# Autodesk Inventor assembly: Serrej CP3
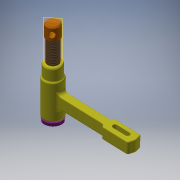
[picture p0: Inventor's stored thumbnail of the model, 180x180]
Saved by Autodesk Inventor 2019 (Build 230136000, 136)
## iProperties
Created: 2019-02
Part Number: Serrej CP3
Material: Générique
Document SubType Name: Assembly
Designer: si-nd67
Author: si-nd67
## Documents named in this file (4)
- E:\ECAM\serrejointsw\Serrej CP3.iam
- E:\ECAM\serrejointsw\Serrej-ACp.iam
- E:\ECAM\serrejointsw\Vis de manoeuvre14.ipt
- E:\ECAM\serrejointsw\Piston14C.ipt
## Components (3 placed, 3 different names)
1. Serrej-ACp:1 [sub-assembly] — Placage:1, 1-Mors-Vis, Angle:1
2. Vis de manoeuvre14:1 — Placage:1, 1-Mors-Vis, Placage:3, Affleurement:1
3. Piston14C:1 — Placage:3, Angle:1, Affleurement:1
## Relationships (5: Mate 3, Angle 1, Flush 1)
- Placage:1 [Mate]: Serrej-ACp:1 ↔ Vis de manoeuvre14:1
- 1-Mors-Vis [Mate]: Serrej-ACp:1 ↔ Vis de manoeuvre14:1
- Placage:3 [Mate]: Vis de manoeuvre14:1 ↔ Piston14C:1
- Angle:1: Serrej-ACp:1 ↔ Piston14C:1
- Affleurement:1 [Flush]: Vis de manoeuvre14:1 ↔ Piston14C:1
